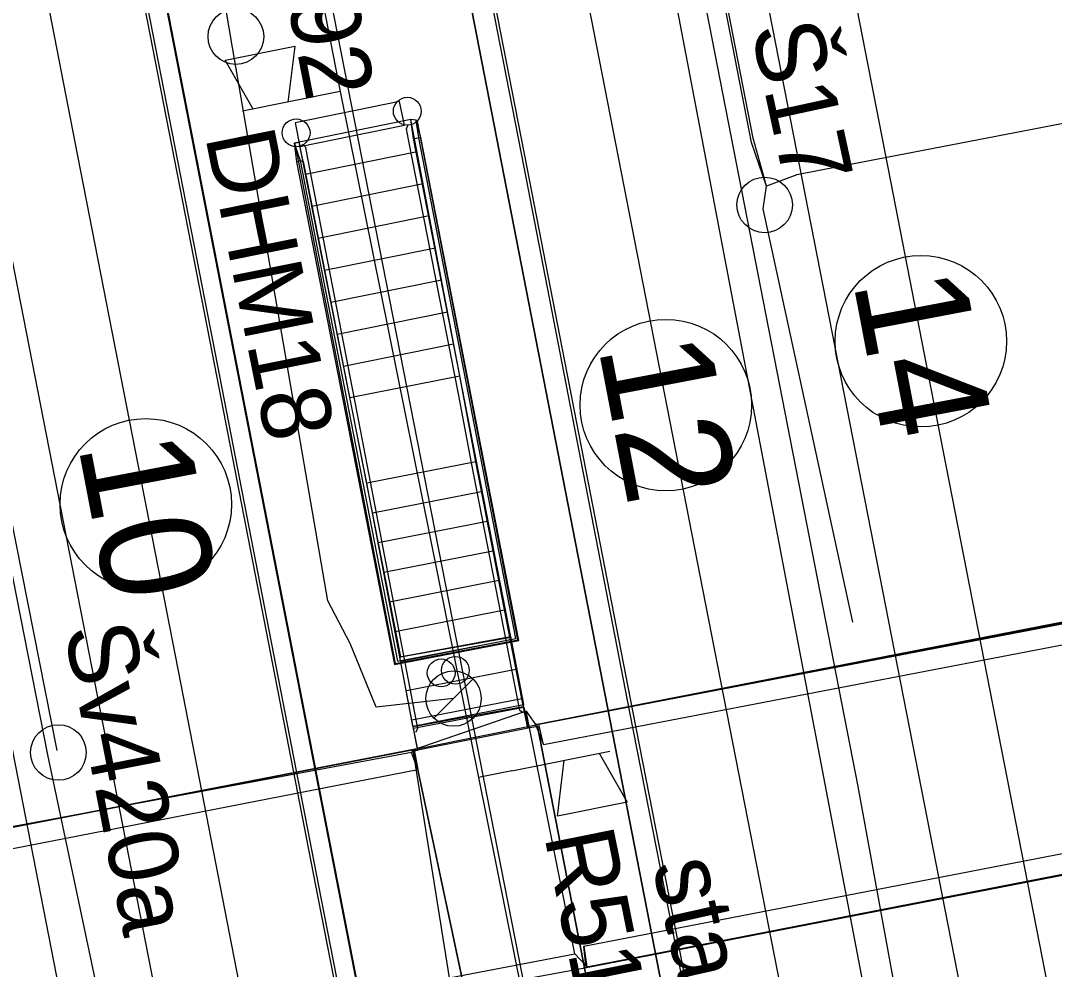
# Model space of a CAD drawing. Extents: x -545736 to -544888, y -1122892 to -1119128.
# Drawn here: x -545152.93 to -545134.33, y -1121892.71 to -1121875.65 of the extents above; entities that cross this region are included whole.
import ezdxf

# ---------------------------------------------------------------- set-up
doc = ezdxf.new("R2010")
doc.units = 0
for name, color, linetype in [('osvětlené plochy-hodnota-obrys', 7, 'Continuous'), ('Podbarveni_Nastupiste', 7, 'Continuous'), ('Podbarveni_Zastreseni_Pozemni', 7, 'Continuous'), ('Vrstva 1 - Koleje', 7, 'Continuous'), ('Vrstva 14_zastreseni a nastupiste', 7, 'Continuous'), ('Vrstva 16_plochy', 7, 'Continuous'), ('Vrstva 17_ploty - zabradli', 7, 'Continuous'), ('Vrstva 18_mosty', 7, 'Continuous'), ('Vrstva 23', 7, 'Continuous'), ('Vrstva 23 - PHS - pozemni - schody - eskalatory', 7, 'Continuous'), ('Vrstva 26', 7, 'Continuous'), ('Vrstva 29 - sdelzar', 7, 'Continuous'), ('Vrstva 33 - prvky sdelzar', 7, 'Continuous'), ('Vrstva 4 - Teren - stezky - prechody - plochy', 7, 'Continuous'), ('Vrstva 43', 7, 'Continuous'), ('Vrstva 44', 7, 'Continuous')]:
    doc.layers.add(name, color=color, linetype=linetype)

msp = doc.modelspace()

# ---------------------------------------------------------------- linework, layer by layer
at = {"layer": 'osvětlené plochy-hodnota-obrys'}
for points in [[(-545137.864, -1121889.42), (-545168.59, -1121731.992), (-545178.308, -1121699.721), (-545197.027, -1121652.528), (-545208.16, -1121619.35), (-545217.952, -1121591.114), (-545225.649, -1121565.547)], [(-545141.742, -1122267.38), (-545105.592, -1122261.055), (-545104.447, -1122260.603), (-545110.322, -1122216.729), (-545115.194, -1122188.84), (-545124.338, -1122134.271), (-545128.334, -1122064.958), (-545124.139, -1121980.114), (-545129.58, -1121934.549), (-545137.864, -1121889.42)]]:
    msp.add_lwpolyline(points, dxfattribs=at)
at = {"layer": 'Podbarveni_Nastupiste'}
for points in [[(-545139.227, -1121934.356), (-545134.81, -1121933.395), (-545135.42, -1121927.458), (-545136.706, -1121917.542), (-545138.218, -1121907.718), (-545140.016, -1121897.812), (-545140.389, -1121895.863), (-545141.913, -1121888.088), (-545143.819, -1121878.288), (-545145.727, -1121868.5), (-545147.633, -1121858.705), (-545149.541, -1121848.922)], [(-545155.195, -1121852.046), (-545153.289, -1121861.829), (-545151.384, -1121871.62), (-545149.473, -1121881.424), (-545147.57, -1121891.206), (-545146.036, -1121899.057), (-545144.88, -1121904.961), (-545142.97, -1121914.762), (-545141.066, -1121924.539), (-545139.66, -1121932.044), (-545139.227, -1121934.356)]]:
    msp.add_lwpolyline(points, dxfattribs=at)
at = {"layer": 'Podbarveni_Zastreseni_Pozemni'}
for points in [[(-545172.521, -1121747.5), (-545175.141, -1121748.003), (-545167.869, -1121785.291), (-545158.018, -1121835.809), (-545145.506, -1121899.971), (-545143.703, -1121909.219), (-545142.244, -1121916.698), (-545139.605, -1121916.178)], [(-545138.929, -1121906.204), (-545140.688, -1121896.644), (-545153.097, -1121832.905)]]:
    msp.add_lwpolyline(points, dxfattribs=at)
at = {"layer": 'Vrstva 1 - Koleje'}
for points in [[(-545148.328, -1121846.526), (-545146.419, -1121856.308), (-545144.514, -1121866.108), (-545142.617, -1121875.856), (-545140.713, -1121885.625), (-545138.778, -1121895.493), (-545136.972, -1121905.274), (-545135.382, -1121915.189), (-545134.029, -1121925.213), (-545133.148, -1121933.125), (-545132.603, -1121939.126)], [(-545157.655, -1121848.546), (-545155.739, -1121858.373), (-545154.911, -1121862.643), (-545153.848, -1121868.103), (-545151.953, -1121877.831), (-545150.049, -1121887.589), (-545148.134, -1121897.423), (-545146.226, -1121907.217), (-545144.322, -1121916.976), (-545142.395, -1121926.865), (-545140.895, -1121934.582), (-545140.428, -1121937.196)], [(-545140.019, -1121864.525), (-545139.058, -1121869.441), (-545137.284, -1121878.534), (-545136.335, -1121883.403), (-545134.555, -1121892.51), (-545133.723, -1121896.779), (-545133.397, -1121898.454)]]:
    msp.add_lwpolyline(points, dxfattribs=at)
for centre in [(-545136.735, -1121881.412), (-545141.323, -1121882.56), (-545150.678, -1121884.345)]:
    msp.add_circle(centre, 1.542, dxfattribs=at)
at = {"layer": 'Vrstva 14_zastreseni a nastupiste'}
for points in [[(-545169.868, -1121746.973), (-545163.039, -1121781.964), (-545153.097, -1121832.905), (-545140.688, -1121896.644), (-545138.929, -1121906.204), (-545137.357, -1121915.755), (-545139.605, -1121916.178), (-545142.252, -1121916.702), (-545143.714, -1121909.203), (-545145.537, -1121899.853), (-545158.037, -1121835.751), (-545167.886, -1121785.244), (-545175.149, -1121747.997), (-545172.521, -1121747.5)], [(-545167.869, -1121785.291), (-545158.018, -1121835.809), (-545145.506, -1121899.971), (-545143.703, -1121909.219), (-545142.244, -1121916.698), (-545139.605, -1121916.178), (-545137.369, -1121915.758), (-545138.929, -1121906.204), (-545140.688, -1121896.644), (-545153.097, -1121832.905), (-545163.04, -1121781.984), (-545169.877, -1121746.971), (-545172.521, -1121747.5), (-545175.141, -1121748.003)]]:
    msp.add_lwpolyline(points, close=True, dxfattribs=at)
for points in [[(-545134.832, -1121933.385), (-545135.475, -1121927.453), (-545136.761, -1121917.537), (-545138.273, -1121907.713), (-545140.071, -1121897.807), (-545140.444, -1121895.858), (-545141.968, -1121888.083), (-545143.874, -1121878.283), (-545145.782, -1121868.495), (-545147.688, -1121858.7), (-545149.596, -1121848.917)], [(-545134.81, -1121933.395), (-545135.42, -1121927.458), (-545136.706, -1121917.542), (-545138.218, -1121907.718), (-545140.016, -1121897.812), (-545140.389, -1121895.863), (-545141.913, -1121888.088), (-545143.819, -1121878.288), (-545145.727, -1121868.5), (-545147.633, -1121858.705), (-545149.541, -1121848.922)], [(-545155.25, -1121852.041), (-545153.344, -1121861.824), (-545151.439, -1121871.615), (-545149.528, -1121881.419), (-545147.625, -1121891.201), (-545146.091, -1121899.052), (-545144.935, -1121904.956), (-545143.025, -1121914.757), (-545141.121, -1121924.534), (-545139.216, -1121934.327)], [(-545155.195, -1121852.046), (-545153.289, -1121861.829), (-545151.384, -1121871.62), (-545149.473, -1121881.424), (-545147.57, -1121891.206), (-545146.036, -1121899.057), (-545144.88, -1121904.961), (-545142.97, -1121914.762), (-545141.066, -1121924.539), (-545139.227, -1121934.356), (-545134.81, -1121933.395)]]:
    msp.add_lwpolyline(points, dxfattribs=at)
for centre in [(-545145.974, -1121877.274), (-545147.973, -1121877.663), (-545145.364, -1121887.377), (-545145.109, -1121887.332)]:
    msp.add_circle(centre, 0.25, dxfattribs=at)
at = {"layer": 'Vrstva 16_plochy'}
for points in [[(-545134.832, -1121933.385), (-545135.475, -1121927.453), (-545136.761, -1121917.537), (-545138.273, -1121907.713), (-545140.071, -1121897.807), (-545140.444, -1121895.858), (-545141.968, -1121888.083), (-545143.874, -1121878.283), (-545145.782, -1121868.495), (-545147.688, -1121858.7), (-545149.596, -1121848.917)], [(-545155.25, -1121852.041), (-545153.344, -1121861.824), (-545151.439, -1121871.615), (-545149.528, -1121881.419), (-545147.625, -1121891.201), (-545146.091, -1121899.052), (-545144.935, -1121904.956), (-545143.025, -1121914.757), (-545141.121, -1121924.534), (-545139.216, -1121934.327), (-545138.162, -1121940.219)], [(-545147.92, -1121877.831), (-545148.011, -1121877.85), (-545147.964, -1121878.184), (-545146.205, -1121887.224), (-545143.964, -1121886.796), (-545145.728, -1121877.747), (-545145.816, -1121877.438), (-545145.908, -1121877.423), (-545147.92, -1121877.831)]]:
    msp.add_lwpolyline(points, dxfattribs=at)
at = {"layer": 'Vrstva 17_ploty - zabradli'}
for points in [[(-545147.991, -1121877.876), (-545146.191, -1121887.207), (-545143.985, -1121886.78), (-545145.791, -1121877.459)], [(-545143.891, -1121888.097), (-545143.952, -1121888.052), (-545144.816, -1121883.601), (-545145.055, -1121882.356), (-545145.952, -1121877.785), (-545145.988, -1121877.59), (-545145.955, -1121877.512)], [(-545145.822, -1121888.446), (-545145.785, -1121888.379), (-545146.636, -1121883.94), (-545146.873, -1121882.696), (-545147.764, -1121878.124), (-545147.8, -1121877.924), (-545147.857, -1121877.869)]]:
    msp.add_lwpolyline(points, dxfattribs=at)
at = {"layer": 'Vrstva 18_mosty'}
for points in [[(-545148.011, -1121877.85), (-545147.964, -1121878.184), (-545146.205, -1121887.224), (-545143.964, -1121886.796), (-545145.728, -1121877.747), (-545145.816, -1121877.438)], [(-545143.915, -1121887.843), (-545144.742, -1121883.58), (-545145.03, -1121882.036), (-545145.908, -1121877.423)], [(-545145.816, -1121877.438), (-545145.908, -1121877.423)], [(-545145.862, -1121877.766), (-545145.908, -1121877.423)], [(-545145.768, -1121877.755), (-545145.816, -1121877.438)], [(-545148.011, -1121877.85), (-545147.92, -1121877.831)], [(-545148.011, -1121877.85), (-545147.901, -1121878.158)], [(-545147.964, -1121878.184), (-545147.901, -1121878.158), (-545146.15, -1121887.165), (-545144.018, -1121886.759), (-545145.768, -1121877.755), (-545145.728, -1121877.747)], [(-545147.844, -1121878.176), (-545147.92, -1121877.831)], [(-545145.784, -1121888.773), (-545145.889, -1121888.226), (-545146.699, -1121883.965), (-545147.009, -1121882.422), (-545147.92, -1121877.831)], [(-545147.901, -1121878.158), (-545147.844, -1121878.176), (-545146.097, -1121887.087), (-545144.112, -1121886.735), (-545145.862, -1121877.766), (-545145.768, -1121877.755)], [(-545145.784, -1121888.773), (-545145.785, -1121888.763), (-545145.859, -1121888.369), (-545145.869, -1121888.339), (-545145.871, -1121888.337), (-545146.108, -1121887.088), (-545144.119, -1121886.724), (-545143.886, -1121887.946), (-545143.891, -1121887.98), (-545143.879, -1121887.995), (-545143.802, -1121888.366), (-545143.63, -1121888.336), (-545143.626, -1121888.339), (-545143.804, -1121888.37), (-545143.915, -1121887.843), (-545145.889, -1121888.226)], [(-545144.119, -1121886.724), (-545144.112, -1121886.735)], [(-545146.108, -1121887.088), (-545146.097, -1121887.087)], [(-545145.871, -1121888.337), (-545143.886, -1121887.946)], [(-545145.869, -1121888.339), (-545143.891, -1121887.98)], [(-545145.859, -1121888.369), (-545143.879, -1121887.995)], [(-545145.785, -1121888.763), (-545143.802, -1121888.366), (-545143.804, -1121888.37)], [(-545142.773, -1121892.747), (-545143.63, -1121888.336)], [(-545143.629, -1121888.336), (-545142.774, -1121892.746)], [(-545145.854, -1121888.783), (-545145.854, -1121888.782), (-545145.785, -1121888.763)], [(-545145.784, -1121888.773), (-545145.852, -1121888.786), (-545145.854, -1121888.783)], [(-545142.773, -1121892.747), (-545142.481, -1121894.207), (-545144.63, -1121894.627), (-545144.924, -1121893.163), (-545145.854, -1121888.782)], [(-545145.854, -1121888.783), (-545144.924, -1121893.161)]]:
    msp.add_lwpolyline(points, dxfattribs=at)
at = {"layer": 'Vrstva 23'}
for p, q in [((-545143.668, -1121888.303), (-545092.208, -1121878.305)), ((-545120.851, -1121883.909), (-545143.623, -1121888.305)), ((-545143.607, -1121888.299), (-545120.835, -1121883.939)), ((-545143.526, -1121888.664), (-545120.759, -1121884.295)), ((-545142.795, -1121892.29), (-545118.037, -1121887.503)), ((-545142.746, -1121892.665), (-545117.967, -1121887.839)), ((-545143.836, -1121888.065), (-545143.668, -1121888.303)), ((-545142.78, -1121892.682), (-545119.878, -1121888.237)), ((-545143.607, -1121888.299), (-545143.623, -1121888.305)), ((-545145.851, -1121888.761), (-545157.851, -1121891.084)), ((-545145.898, -1121888.812), (-545157.848, -1121891.032)), ((-545145.802, -1121888.742), (-545157.832, -1121891.078)), ((-545145.871, -1121888.769), (-545145.898, -1121888.812)), ((-545157.719, -1121891.445), (-545145.786, -1121889.113)), ((-545142.962, -1121892.429), (-545142.764, -1121892.639)), ((-545142.746, -1121892.665), (-545142.78, -1121892.682))]:
    msp.add_line(p, q, dxfattribs=at)
for points in [[(-545145.222, -1121892.862), (-545142.962, -1121892.429), (-545143.836, -1121888.065), (-545145.871, -1121888.769)], [(-545143.526, -1121888.664), (-545143.607, -1121888.299), (-545143.668, -1121888.303)], [(-545145.851, -1121888.761), (-545145.786, -1121889.113), (-545145.898, -1121888.812)], [(-545142.764, -1121892.639), (-545142.795, -1121892.29), (-545142.746, -1121892.665)]]:
    msp.add_lwpolyline(points, close=True, dxfattribs=at)
for points in [[(-545145.851, -1121888.761), (-545145.802, -1121888.742), (-545143.623, -1121888.305)], [(-545144.624, -1121892.987), (-545144.621, -1121893.059), (-545144.004, -1121892.918), (-545143.987, -1121892.905), (-545142.78, -1121892.682)]]:
    msp.add_lwpolyline(points, dxfattribs=at)
at = {"layer": 'Vrstva 23 - PHS - pozemni - schody - eskalatory'}
for points in [[(-545143.915, -1121887.843), (-545144.742, -1121883.58), (-545145.03, -1121882.036), (-545145.908, -1121877.423), (-545147.92, -1121877.831)], [(-545147.009, -1121882.422), (-545147.92, -1121877.831)], [(-545147.806, -1121878.407), (-545145.798, -1121877.999)], [(-545147.691, -1121878.983), (-545145.689, -1121878.576)], [(-545147.577, -1121879.559), (-545145.579, -1121879.152)], [(-545147.463, -1121880.134), (-545145.469, -1121879.729)], [(-545147.349, -1121880.711), (-545145.359, -1121880.305)], [(-545147.234, -1121881.286), (-545145.25, -1121880.883)], [(-545147.12, -1121881.862), (-545145.14, -1121881.459)], [(-545143.915, -1121887.843), (-545145.889, -1121888.226), (-545146.699, -1121883.965), (-545147.009, -1121882.422), (-545145.03, -1121882.036), (-545145.03, -1121882.036)], [(-545144.742, -1121883.58), (-545146.699, -1121883.965)], [(-545146.598, -1121884.498), (-545144.639, -1121884.113)], [(-545146.496, -1121885.032), (-545144.535, -1121884.646)], [(-545146.395, -1121885.565), (-545144.432, -1121885.179)], [(-545146.293, -1121886.098), (-545144.328, -1121885.712)], [(-545146.192, -1121886.632), (-545144.225, -1121886.244)], [(-545146.091, -1121887.166), (-545144.122, -1121886.777)], [(-545145.99, -1121887.696), (-545144.018, -1121887.31)]]:
    msp.add_lwpolyline(points, dxfattribs=at)
at = {"layer": 'Vrstva 26'}
msp.add_lwpolyline([(-545166.504, -1121815.685), (-545166.698, -1121816.037), (-545161.721, -1121841.823), (-545157.777, -1121861.768), (-545157.507, -1121863.136), (-545152.448, -1121888.853), (-545147.998, -1121909.917), (-545148.049, -1121912.578), (-545147.648, -1121914.128), (-545146.343, -1121921.072), (-545145.879, -1121923.54), (-545145.457, -1121924.088), (-545144.44, -1121929.853), (-545143.295, -1121935.716), (-545143.648, -1121936.405), (-545143.018, -1121939.014), (-545142.006, -1121940.631), (-545141.059, -1121947.169), (-545140.841, -1121950.653), (-545139.922, -1121952.292)], dxfattribs=at)
at = {"layer": 'Vrstva 29 - sdelzar'}
for p, q in [((-545141.41, -1121905.52), (-545168.73, -1121766.29)), ((-545144.09, -1121889.14), (-545144.69, -1121889.26))]:
    msp.add_line(p, q, dxfattribs=at)
msp.add_lwpolyline([(-545171.97, -1121749.47), (-545172.03, -1121749.33), (-545171.59, -1121751.6), (-545168.26, -1121768.68), (-545164.8, -1121786.45), (-545161.35, -1121804.17), (-545161.26, -1121804.64), (-545158.15, -1121820.62), (-545154.88, -1121837.37), (-545151.57, -1121854.39), (-545148.31, -1121871.12), (-545147.18, -1121876.92), (-545144.69, -1121889.26), (-545140.92, -1121907.97), (-545141.94, -1121907.98)], dxfattribs=at)
at = {"layer": 'Vrstva 33 - prvky sdelzar'}
for p, q in [((-545147.18, -1121876.92), (-545148.937, -1121877.274)), ((-545144.09, -1121889.14), (-545142.333, -1121888.786))]:
    msp.add_line(p, q, dxfattribs=at)
for points in [[(-545148.748, -1121877.236), (-545149.252, -1121876.358), (-545147.997, -1121876.105), (-545148.121, -1121877.11)], [(-545142.522, -1121888.824), (-545142.018, -1121889.702), (-545143.273, -1121889.955), (-545143.149, -1121888.95)]]:
    msp.add_lwpolyline(points, dxfattribs=at)
msp.add_lwpolyline([(-545147.991, -1121877.482), (-545147.905, -1121877.906), (-545146.026, -1121877.524), (-545146.112, -1121877.1)], close=True, dxfattribs=at)
at = {"layer": 'Vrstva 4 - Teren - stezky - prechody - plochy'}
for points in [[(-545188.763, -1121698.109), (-545188.641, -1121698.826), (-545185.213, -1121715.136), (-545181.647, -1121733.399), (-545177.117, -1121756.524), (-545170.416, -1121791.087), (-545164.311, -1121822.524), (-545157.023, -1121859.828), (-545149.915, -1121896.158), (-545142.13, -1121936.158), (-545141.676, -1121939.159), (-545141.157, -1121942.596), (-545141.923, -1121943.776)], [(-545141.923, -1121943.776), (-545142.097, -1121942.982), (-545141.665, -1121942.659), (-545141.923, -1121941.346), (-545142.767, -1121941.354), (-545151.586, -1121896.379), (-545158.808, -1121859.367), (-545165.97, -1121822.744), (-545172.05, -1121791.327), (-545183.361, -1121733.476), (-545187.416, -1121715.505), (-545191.632, -1121699.681), (-545191.805, -1121699.137)], [(-545130.358, -1121950.008), (-545129.391, -1121949.959), (-545129.73, -1121942.596), (-545130.115, -1121934.948), (-545130.824, -1121927.405), (-545131.836, -1121918.196), (-545133.344, -1121907.479), (-545134.953, -1121898.499), (-545142.937, -1121857.697), (-545151.741, -1121812.566), (-545162.39, -1121757.819), (-545164.226, -1121748.401), (-545166.939, -1121735.985), (-545169.746, -1121724.99), (-545172.237, -1121716.559), (-545173.733, -1121711.673), (-545173.909, -1121711.118), (-545175.871, -1121711.785), (-545175.683, -1121712.485)], [(-545130.358, -1121950.008), (-545130.752, -1121943), (-545131.52, -1121935.35), (-545132.155, -1121927.829), (-545133.341, -1121918.921), (-545135.127, -1121907.455), (-545136.587, -1121899.196), (-545144.41, -1121858.134), (-545153.364, -1121812.756), (-545162.564, -1121765.529), (-545165.788, -1121749.365), (-545168.396, -1121737.4), (-545171.828, -1121724.869), (-545174.108, -1121717.697), (-545175.683, -1121712.485)], [(-545134.407, -1121939.39), (-545134.81, -1121933.395), (-545135.42, -1121927.458), (-545136.706, -1121917.542), (-545138.218, -1121907.718), (-545140.016, -1121897.812), (-545140.389, -1121895.863), (-545141.913, -1121888.088), (-545143.819, -1121878.288), (-545145.727, -1121868.5), (-545147.633, -1121858.705), (-545149.541, -1121848.922)], [(-545155.195, -1121852.046), (-545153.289, -1121861.829), (-545151.384, -1121871.62), (-545149.473, -1121881.424), (-545147.57, -1121891.206), (-545146.036, -1121899.057), (-545144.88, -1121904.961), (-545142.97, -1121914.762), (-545141.066, -1121924.539), (-545139.227, -1121934.356)]]:
    msp.add_lwpolyline(points, dxfattribs=at)
at = {"layer": 'Vrstva 43'}
msp.add_line((-545145.495, -1121888.191), (-545144.79, -1121887.487), dxfattribs=at)
for centre, radius in [((-545149.057, -1121875.932), 0.5), ((-545139.545, -1121878.96), 0.5), ((-545145.142, -1121887.84), 0.498), ((-545152.25, -1121888.81), 0.5)]:
    msp.add_circle(centre, radius, dxfattribs=at)
at = {"layer": 'Vrstva 44'}
for points in [[(-545139.513, -1121878.622), (-545139.749, -1121877.759), (-545147.249, -1121839.292), (-545147.369, -1121839.002), (-545147.48, -1121838.112), (-545155.446, -1121797.363), (-545155.595, -1121796.474), (-545155.706, -1121795.975), (-545161.592, -1121765.233), (-545161.723, -1121764.693), (-545161.847, -1121763.916), (-545167.672, -1121738.027), (-545170.022, -1121727.953), (-545170.129, -1121727.27), (-545170.34, -1121725.169), (-545172.277, -1121718.871), (-545175.906, -1121708.217), (-545178.967, -1121700.134), (-545179.343, -1121699.618)], [(-545094.826, -1121887.512), (-545094.254, -1121887.557), (-545092.865, -1121887.668), (-545091.72, -1121887.758), (-545090.268, -1121887.873), (-545086.549, -1121888.168), (-545079.866, -1121888.698), (-545079.307, -1121888.256), (-545078.235, -1121887.388), (-545078.119, -1121886.246), (-545076.573, -1121871.721), (-545077.268, -1121870.044), (-545079.088, -1121869.124), (-545086.504, -1121868.907), (-545093.818, -1121869.676), (-545108.699, -1121872.648), (-545109.324, -1121872.781), (-545110.052, -1121872.845), (-545138.969, -1121878.416), (-545139.513, -1121878.622), (-545139.779, -1121877.836), (-545147.175, -1121839.811)], [(-545149.12, -1121876.13), (-545150.552, -1121867.677), (-545152.211, -1121859.59), (-545155.524, -1121842.636), (-545155.851, -1121841.002), (-545155.936, -1121840.605)], [(-545152.27, -1121888.776), (-545157.334, -1121863.209), (-545157.36, -1121862.906), (-545157.668, -1121862.934), (-545165.372, -1121864.322), (-545165.72, -1121864.354)], [(-545145.143, -1121887.839), (-545145.143, -1121887.839), (-545146.535, -1121887.991), (-545147.002, -1121886.846), (-545147.405, -1121886.082), (-545149.12, -1121876.13)], [(-545137.958, -1121886.463), (-545139.57, -1121879.03), (-545139.513, -1121878.622)]]:
    msp.add_lwpolyline(points, dxfattribs=at)

# ---------------------------------------------------------------- texts
at = {"layer": 'Vrstva 1 - Koleje'}
for s, p in [('14', (-545137.958, -1121880.338)), ('12', (-545142.542, -1121881.509)), ('10', (-545151.9, -1121883.274))]:
    msp.add_text(s, height=2, rotation=280.8048, dxfattribs=at).set_placement(p)
at = {"layer": 'Vrstva 33 - prvky sdelzar'}
for s, p in [('DHM18', (-545149.613, -1121877.724)), ('R510', (-545143.512, -1121890.308))]:
    msp.add_text(s, height=1.25, rotation=281.3986, dxfattribs=at).set_placement(p)
at = {"layer": 'Vrstva 43'}
for s, rotation, p in [('Š92', 281.0281, (-545148.344, -1121874.213)), ('Š17', 282.2363, (-545139.794, -1121875.783)), ('Šv420a', 281.0323, (-545152.15, -1121886.59)), ('stará šachta', 282.6444, (-545141.567, -1121890.833))]:
    msp.add_text(s, height=1.25, rotation=rotation, dxfattribs=at).set_placement(p)

doc.saveas('drawing.dxf')
